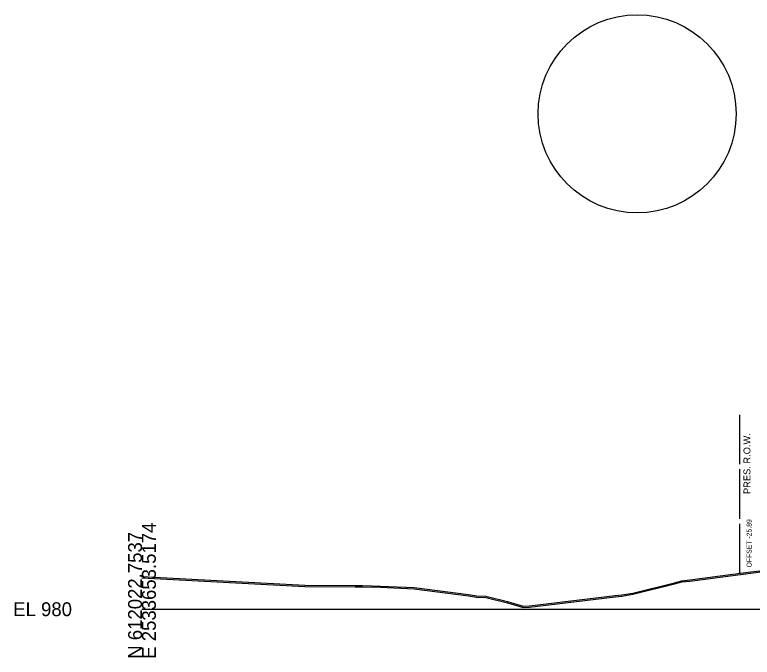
# Model space of a CAD drawing. Extents: x -26 to 303, y -23 to 1542.
# Drawn here: x -25.7 to 123.2, y -9.7 to 120 of the extents above; entities that cross this region are included whole.
import ezdxf

# ---------------------------------------------------------------- set-up
doc = ezdxf.new("R2010")
doc.units = 0
for name, color, linetype in [('DESIGN - SCRATCH - User 1', 7, 'Continuous'), ('DESIGN - SHEET - Light Grid', 7, 'Continuous'), ('DESIGN - TYPICAL - Slope Tie Text', 7, 'Continuous'), ('SURVEY - GROUND - Bottom of Topsoil Layer', 7, 'Continuous'), ('SURVEY - GROUND - Top of Ground', 7, 'Continuous'), ('SURVEY - PROPERTY - ROW Lines', 7, 'Continuous'), ('SURVEY - PROPERTY - ROW Lines Text', 7, 'Continuous')]:
    doc.layers.add(name, color=color, linetype=linetype)

msp = doc.modelspace()

# ---------------------------------------------------------------- linework, layer by layer
at = {"layer": 'DESIGN - SCRATCH - User 1'}
msp.add_circle((100, 100), 20, dxfattribs=at)
at = {"layer": 'DESIGN - SHEET - Light Grid'}
msp.add_line((0, 0), (150, 0), dxfattribs=at)
at = {"layer": 'SURVEY - GROUND - Bottom of Topsoil Layer'}
for p, q in [((122.93, 7.28), (125.97, 7.65)), ((0, 6.34), (32.86, 4.59)), ((110.63, 5.67), (119.3, 6.83)), ((119.3, 6.83), (122.93, 7.28)), ((32.86, 4.59), (43.06, 4.53)), ((43.06, 4.53), (44.55, 4.51)), ((44.55, 4.51), (48.16, 4.43)), ((99.1, 3.01), (107.52, 5.11)), ((107.52, 5.11), (109.06, 5.51)), ((109.06, 5.51), (110.63, 5.67)), ((48.16, 4.43), (54.94, 4.14)), ((54.94, 4.14), (65.94, 2.73)), ((96.91, 2.66), (99.1, 3.01)), ((65.94, 2.73), (67.59, 2.45)), ((67.59, 2.45), (69.42, 2.38)), ((69.42, 2.38), (73.81, 1.29)), ((78.25, 0.41), (95.55, 2.52)), ((95.55, 2.52), (96.91, 2.66)), ((73.81, 1.29), (76.96, 0.36)), ((76.96, 0.36), (78.25, 0.41))]:
    msp.add_line(p, q, dxfattribs=at)
at = {"layer": 'SURVEY - GROUND - Top of Ground'}
msp.add_lwpolyline([(0, 6.59), (32.86, 4.84), (43.06, 4.78), (44.55, 4.76), (48.16, 4.68), (54.94, 4.39), (65.94, 2.98), (67.59, 2.7), (69.42, 2.63), (73.81, 1.54), (76.96, 0.61), (78.25, 0.66), (95.55, 2.77), (96.91, 2.91), (99.1, 3.26), (107.52, 5.36), (109.06, 5.76), (110.63, 5.92), (119.3, 7.08), (122.93, 7.53), (125.97, 7.9)], dxfattribs=at)
at = {"layer": 'SURVEY - PROPERTY - ROW Lines'}
for p, q in [((120.73, 29.26), (120.73, 39.26)), ((120.73, 18.26), (120.73, 28.26)), ((120.73, 7.26), (120.73, 17.26))]:
    msp.add_line(p, q, dxfattribs=at)

# ---------------------------------------------------------------- texts
at = {"layer": 'DESIGN - SHEET - Light Grid'}
for s, p in [('E 2533653.5174', (2.8, -10)), ('N 612022.7537', (0, -10))]:
    msp.add_text(s, height=2.8, rotation=90, dxfattribs=at).set_placement(p)
msp.add_text('EL 980', height=2.8, dxfattribs=at).set_placement((-26, -1.4))
at = {"layer": 'DESIGN - TYPICAL - Slope Tie Text'}
msp.add_text('OFFSET -25.89', height=1, rotation=90, dxfattribs=at).set_placement((123.11, 8.43))
at = {"layer": 'SURVEY - PROPERTY - ROW Lines Text'}
msp.add_text('PRES. R.O.W.', height=1.4, rotation=90, dxfattribs=at).set_placement((122.88, 23.26))

doc.saveas('drawing.dxf')
